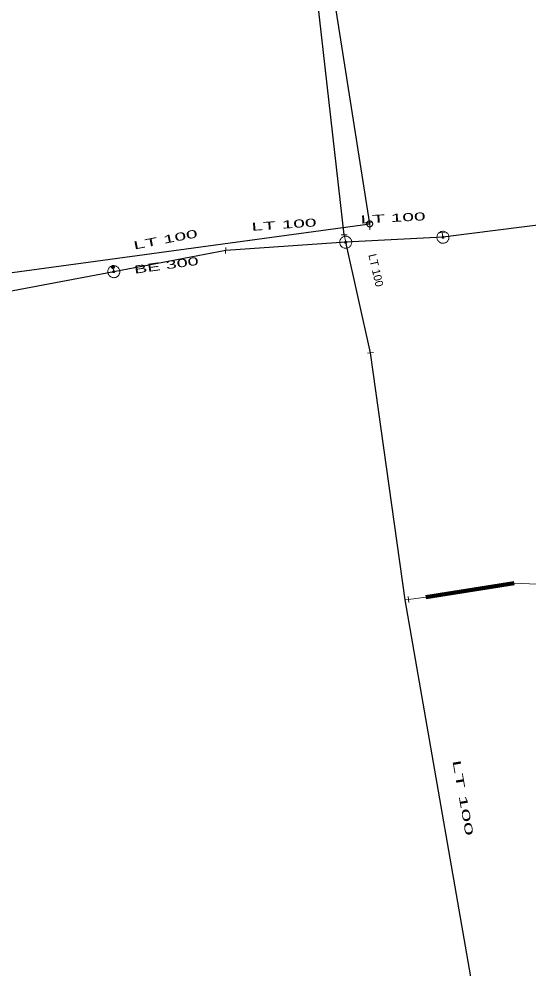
# Model space of a CAD drawing. Extents: x -687515 to -686506, y -974029 to -973461.
# Drawn here: x -687253.9 to -687211.4, y -973757.5 to -973678.4 of the extents above; entities that cross this region are included whole.
import ezdxf
from ezdxf.enums import TextEntityAlignment as Align

# ---------------------------------------------------------------- set-up
doc = ezdxf.new("R2010")
doc.units = 0
doc.header["$LTSCALE"] = 0.27
for name, color, linetype, lineweight in [('1', 7, 'Continuous', 13), ('13', 7, 'Continuous', 13), ('14', 7, 'Continuous', 25), ('17', 7, 'Continuous', 25), ('22', 7, 'Continuous', 13), ('3', 7, 'Continuous', 106), ('34', 7, 'Continuous', 13), ('47', 7, 'Continuous', 13), ('9', 7, 'Continuous', 13)]:
    doc.layers.add(name, color=color, linetype=linetype, lineweight=lineweight)

msp = doc.modelspace()

# ---------------------------------------------------------------- linework, layer by layer
at = {"layer": '13'}
msp.add_lwpolyline([(-687221.46, -973726.734), (-687220.01, -973726.539), (-687212.67, -973725.37), (-687210.76, -973725.46), (-687209.649, -973725.949), (-687209.469, -973727.689)], dxfattribs=at)
at = {"layer": '14'}
for p, q in [((-687224.684, -973695.454), (-687232.568, -973645.041)), ((-687258.796, -973700.107), (-687224.684, -973695.454))]:
    msp.add_line(p, q, dxfattribs=at)
at = {"layer": '14', "lineweight": 13}
for p, q in [((-687218.64, -973696.182), (-687218.589, -973696.579)), ((-687226.678, -973696.992), (-687226.809, -973696.379)), ((-687246.051, -973699.048), (-687245.977, -973699.441)), ((-687221.719, -973726.77), (-687221.46, -973726.734))]:
    msp.add_line(p, q, dxfattribs=at)
at = {"layer": '17'}
for p, q in [((-687152.206, -973687.982), (-687218.589, -973696.579)), ((-687226.678, -973696.992), (-687236.665, -973697.682)), ((-687218.589, -973696.579), (-687226.678, -973696.992)), ((-687224.609, -973706.199), (-687226.678, -973696.992)), ((-687236.665, -973697.682), (-687245.977, -973699.441))]:
    msp.add_line(p, q, dxfattribs=at)
for points in [[(-687226.809, -973696.379), (-687231.379, -973655.94), (-687231.546, -973653.623), (-687238.835, -973599.816), (-687148.873, -973581.4)], [(-687245.977, -973699.441), (-687281.864, -973706.221), (-687329.026, -973714.296), (-687356.324, -973710.759), (-687364.106, -973711.207)], [(-687215.094, -973764.848), (-687221.719, -973726.77), (-687224.609, -973706.199)]]:
    msp.add_lwpolyline(points, dxfattribs=at)
at = {"layer": '22'}
msp.add_line((-687224.683, -973695.202), (-687224.684, -973695.946), dxfattribs=at)
msp.add_lwpolyline([(-687224.432, -973695.454), (-687224.433, -973695.428), (-687224.437, -973695.402), (-687224.443, -973695.376), (-687224.453, -973695.352), (-687224.465, -973695.328), (-687224.479, -973695.306), (-687224.496, -973695.285), (-687224.514, -973695.267), (-687224.535, -973695.25), (-687224.557, -973695.236), (-687224.581, -973695.224), (-687224.605, -973695.214), (-687224.631, -973695.208), (-687224.657, -973695.204), (-687224.683, -973695.202), (-687224.709, -973695.203), (-687224.735, -973695.207), (-687224.761, -973695.213), (-687224.786, -973695.223), (-687224.809, -973695.235), (-687224.831, -973695.249), (-687224.852, -973695.266), (-687224.87, -973695.284), (-687224.887, -973695.305), (-687224.901, -973695.327), (-687224.913, -973695.351), (-687224.923, -973695.375), (-687224.93, -973695.401), (-687224.934, -973695.427), (-687224.936, -973695.453), (-687224.935, -973695.479), (-687224.931, -973695.505), (-687224.924, -973695.531), (-687224.914, -973695.556), (-687224.902, -973695.579), (-687224.888, -973695.601), (-687224.871, -973695.622), (-687224.853, -973695.64), (-687224.832, -973695.657), (-687224.81, -973695.671), (-687224.787, -973695.683), (-687224.762, -973695.693), (-687224.736, -973695.7), (-687224.71, -973695.704), (-687224.684, -973695.706), (-687224.658, -973695.705), (-687224.632, -973695.701), (-687224.606, -973695.694), (-687224.582, -973695.684), (-687224.558, -973695.672), (-687224.536, -973695.658), (-687224.515, -973695.641), (-687224.497, -973695.623), (-687224.48, -973695.602), (-687224.466, -973695.58), (-687224.454, -973695.557), (-687224.444, -973695.532), (-687224.438, -973695.506), (-687224.434, -973695.48)], close=True, dxfattribs=at)
at = {"layer": '3'}
msp.add_line((-687220.01, -973726.54), (-687212.67, -973725.37), dxfattribs=at)
at = {"layer": '3', "lineweight": 100}
msp.add_line((-687220.01, -973726.54), (-687212.67, -973725.37), dxfattribs=at)
at = {"layer": '34'}
for p, q in [((-687218.885, -973696.215), (-687218.394, -973696.148)), ((-687226.561, -973696.385), (-687227.056, -973696.372)), ((-687236.671, -973697.929), (-687236.658, -973697.434)), ((-687224.855, -973706.221), (-687224.362, -973706.176)), ((-687221.426, -973726.979), (-687221.493, -973726.488))]:
    msp.add_line(p, q, dxfattribs=at)
at = {"layer": '47'}
for points in [[(-687218.093, -973696.514), (-687218.102, -973696.463), (-687218.117, -973696.412), (-687218.137, -973696.365), (-687218.161, -973696.318), (-687218.191, -973696.275), (-687218.226, -973696.235), (-687218.264, -973696.199), (-687218.305, -973696.168), (-687218.349, -973696.14), (-687218.396, -973696.117), (-687218.446, -973696.099), (-687218.497, -973696.088), (-687218.548, -973696.08), (-687218.601, -973696.079), (-687218.653, -973696.083), (-687218.704, -973696.092), (-687218.755, -973696.107), (-687218.803, -973696.127), (-687218.849, -973696.151), (-687218.892, -973696.181), (-687218.932, -973696.216), (-687218.969, -973696.254), (-687219, -973696.295), (-687219.028, -973696.339), (-687219.05, -973696.386), (-687219.068, -973696.436), (-687219.08, -973696.487), (-687219.087, -973696.538), (-687219.088, -973696.591), (-687219.084, -973696.643), (-687219.075, -973696.694), (-687219.06, -973696.745), (-687219.041, -973696.794), (-687219.016, -973696.839), (-687218.986, -973696.882), (-687218.952, -973696.922), (-687218.914, -973696.959), (-687218.873, -973696.991), (-687218.828, -973697.018), (-687218.781, -973697.04), (-687218.731, -973697.058), (-687218.681, -973697.071), (-687218.629, -973697.077), (-687218.576, -973697.078), (-687218.524, -973697.074), (-687218.473, -973697.065), (-687218.422, -973697.05), (-687218.374, -973697.031), (-687218.328, -973697.006), (-687218.285, -973696.976), (-687218.245, -973696.942), (-687218.209, -973696.904), (-687218.177, -973696.863), (-687218.15, -973696.818), (-687218.127, -973696.771), (-687218.109, -973696.721), (-687218.097, -973696.671), (-687218.09, -973696.619), (-687218.089, -973696.566)], [(-687226.182, -973696.927), (-687226.191, -973696.876), (-687226.206, -973696.825), (-687226.226, -973696.778), (-687226.25, -973696.731), (-687226.28, -973696.688), (-687226.315, -973696.648), (-687226.353, -973696.612), (-687226.394, -973696.581), (-687226.438, -973696.553), (-687226.485, -973696.53), (-687226.535, -973696.512), (-687226.586, -973696.501), (-687226.637, -973696.493), (-687226.69, -973696.492), (-687226.742, -973696.496), (-687226.793, -973696.505), (-687226.844, -973696.52), (-687226.892, -973696.54), (-687226.938, -973696.564), (-687226.981, -973696.594), (-687227.021, -973696.629), (-687227.058, -973696.667), (-687227.089, -973696.708), (-687227.117, -973696.752), (-687227.139, -973696.799), (-687227.157, -973696.849), (-687227.169, -973696.9), (-687227.176, -973696.951), (-687227.177, -973697.004), (-687227.173, -973697.056), (-687227.164, -973697.107), (-687227.149, -973697.158), (-687227.13, -973697.207), (-687227.105, -973697.252), (-687227.075, -973697.295), (-687227.041, -973697.335), (-687227.003, -973697.372), (-687226.962, -973697.404), (-687226.917, -973697.431), (-687226.87, -973697.453), (-687226.82, -973697.471), (-687226.77, -973697.484), (-687226.718, -973697.49), (-687226.665, -973697.491), (-687226.613, -973697.487), (-687226.562, -973697.478), (-687226.511, -973697.463), (-687226.463, -973697.444), (-687226.417, -973697.419), (-687226.374, -973697.389), (-687226.334, -973697.355), (-687226.298, -973697.317), (-687226.266, -973697.276), (-687226.239, -973697.231), (-687226.216, -973697.184), (-687226.198, -973697.134), (-687226.186, -973697.084), (-687226.179, -973697.032), (-687226.178, -973696.979)], [(-687226.596, -973696.981), (-687226.597, -973696.972), (-687226.6, -973696.964), (-687226.603, -973696.957), (-687226.607, -973696.949), (-687226.612, -973696.942), (-687226.618, -973696.935), (-687226.624, -973696.929), (-687226.631, -973696.924), (-687226.638, -973696.92), (-687226.646, -973696.916), (-687226.654, -973696.913), (-687226.663, -973696.911), (-687226.671, -973696.91), (-687226.679, -973696.909), (-687226.688, -973696.91), (-687226.697, -973696.911), (-687226.705, -973696.914), (-687226.712, -973696.917), (-687226.72, -973696.921), (-687226.727, -973696.926), (-687226.734, -973696.932), (-687226.74, -973696.938), (-687226.745, -973696.945), (-687226.75, -973696.953), (-687226.753, -973696.96), (-687226.756, -973696.968), (-687226.758, -973696.977), (-687226.759, -973696.985), (-687226.76, -973696.993), (-687226.759, -973697.002), (-687226.758, -973697.011), (-687226.755, -973697.019), (-687226.752, -973697.026), (-687226.748, -973697.034), (-687226.743, -973697.041), (-687226.738, -973697.048), (-687226.731, -973697.054), (-687226.724, -973697.059), (-687226.716, -973697.064), (-687226.709, -973697.067), (-687226.701, -973697.07), (-687226.692, -973697.072), (-687226.684, -973697.073), (-687226.676, -973697.074), (-687226.667, -973697.073), (-687226.658, -973697.072), (-687226.65, -973697.069), (-687226.643, -973697.066), (-687226.635, -973697.062), (-687226.628, -973697.057), (-687226.621, -973697.052), (-687226.615, -973697.045), (-687226.61, -973697.038), (-687226.606, -973697.031), (-687226.602, -973697.023), (-687226.599, -973697.015), (-687226.597, -973697.006), (-687226.596, -973696.998), (-687226.595, -973696.99)], [(-687218.507, -973696.568), (-687218.508, -973696.559), (-687218.511, -973696.551), (-687218.514, -973696.544), (-687218.518, -973696.536), (-687218.523, -973696.529), (-687218.529, -973696.522), (-687218.535, -973696.516), (-687218.542, -973696.511), (-687218.549, -973696.507), (-687218.557, -973696.503), (-687218.565, -973696.5), (-687218.574, -973696.498), (-687218.582, -973696.497), (-687218.59, -973696.496), (-687218.599, -973696.497), (-687218.608, -973696.498), (-687218.616, -973696.501), (-687218.623, -973696.504), (-687218.631, -973696.508), (-687218.638, -973696.513), (-687218.645, -973696.519), (-687218.651, -973696.525), (-687218.656, -973696.532), (-687218.661, -973696.54), (-687218.664, -973696.547), (-687218.667, -973696.555), (-687218.669, -973696.564), (-687218.67, -973696.572), (-687218.671, -973696.58), (-687218.67, -973696.589), (-687218.669, -973696.598), (-687218.666, -973696.606), (-687218.663, -973696.613), (-687218.659, -973696.621), (-687218.654, -973696.628), (-687218.649, -973696.635), (-687218.642, -973696.641), (-687218.635, -973696.646), (-687218.627, -973696.651), (-687218.62, -973696.654), (-687218.612, -973696.657), (-687218.603, -973696.659), (-687218.595, -973696.66), (-687218.587, -973696.661), (-687218.578, -973696.66), (-687218.569, -973696.659), (-687218.561, -973696.656), (-687218.554, -973696.653), (-687218.546, -973696.649), (-687218.539, -973696.644), (-687218.532, -973696.639), (-687218.526, -973696.632), (-687218.521, -973696.625), (-687218.517, -973696.618), (-687218.513, -973696.61), (-687218.51, -973696.602), (-687218.508, -973696.593), (-687218.507, -973696.585), (-687218.506, -973696.577)], [(-687245.481, -973699.376), (-687245.49, -973699.325), (-687245.505, -973699.274), (-687245.525, -973699.227), (-687245.549, -973699.18), (-687245.579, -973699.137), (-687245.614, -973699.097), (-687245.652, -973699.061), (-687245.693, -973699.03), (-687245.737, -973699.002), (-687245.784, -973698.979), (-687245.834, -973698.961), (-687245.885, -973698.95), (-687245.936, -973698.942), (-687245.989, -973698.941), (-687246.041, -973698.945), (-687246.092, -973698.954), (-687246.143, -973698.969), (-687246.191, -973698.989), (-687246.237, -973699.013), (-687246.28, -973699.043), (-687246.32, -973699.078), (-687246.357, -973699.116), (-687246.388, -973699.157), (-687246.416, -973699.201), (-687246.438, -973699.248), (-687246.456, -973699.298), (-687246.468, -973699.349), (-687246.475, -973699.4), (-687246.476, -973699.453), (-687246.472, -973699.505), (-687246.463, -973699.556), (-687246.448, -973699.607), (-687246.429, -973699.656), (-687246.404, -973699.701), (-687246.374, -973699.744), (-687246.34, -973699.784), (-687246.302, -973699.821), (-687246.261, -973699.853), (-687246.216, -973699.88), (-687246.169, -973699.902), (-687246.119, -973699.92), (-687246.069, -973699.933), (-687246.017, -973699.939), (-687245.964, -973699.94), (-687245.912, -973699.936), (-687245.861, -973699.927), (-687245.81, -973699.912), (-687245.762, -973699.893), (-687245.716, -973699.868), (-687245.673, -973699.838), (-687245.633, -973699.804), (-687245.597, -973699.766), (-687245.565, -973699.725), (-687245.538, -973699.68), (-687245.515, -973699.633), (-687245.497, -973699.583), (-687245.485, -973699.533), (-687245.478, -973699.481), (-687245.477, -973699.428)], [(-687245.895, -973699.43), (-687245.896, -973699.421), (-687245.899, -973699.413), (-687245.902, -973699.406), (-687245.906, -973699.398), (-687245.911, -973699.391), (-687245.917, -973699.384), (-687245.923, -973699.378), (-687245.93, -973699.373), (-687245.937, -973699.369), (-687245.945, -973699.365), (-687245.953, -973699.362), (-687245.962, -973699.36), (-687245.97, -973699.359), (-687245.978, -973699.358), (-687245.987, -973699.359), (-687245.996, -973699.36), (-687246.004, -973699.363), (-687246.011, -973699.366), (-687246.019, -973699.37), (-687246.026, -973699.375), (-687246.033, -973699.381), (-687246.039, -973699.387), (-687246.044, -973699.394), (-687246.049, -973699.402), (-687246.052, -973699.409), (-687246.055, -973699.417), (-687246.057, -973699.426), (-687246.058, -973699.434), (-687246.059, -973699.442), (-687246.058, -973699.451), (-687246.057, -973699.46), (-687246.054, -973699.468), (-687246.051, -973699.475), (-687246.047, -973699.483), (-687246.042, -973699.49), (-687246.037, -973699.497), (-687246.03, -973699.503), (-687246.023, -973699.508), (-687246.015, -973699.513), (-687246.008, -973699.516), (-687246, -973699.519), (-687245.991, -973699.521), (-687245.983, -973699.522), (-687245.975, -973699.523), (-687245.966, -973699.522), (-687245.957, -973699.521), (-687245.949, -973699.518), (-687245.942, -973699.515), (-687245.934, -973699.511), (-687245.927, -973699.506), (-687245.92, -973699.501), (-687245.914, -973699.494), (-687245.909, -973699.487), (-687245.905, -973699.48), (-687245.901, -973699.472), (-687245.898, -973699.464), (-687245.896, -973699.455), (-687245.895, -973699.447), (-687245.894, -973699.439)]]:
    msp.add_lwpolyline(points, close=True, dxfattribs=at)
at = {"layer": '9'}
for points in [[(-687245.924, -973699.048), (-687245.926, -973699.034), (-687245.928, -973699.022), (-687245.931, -973699.009), (-687245.936, -973698.997), (-687245.941, -973698.985), (-687245.949, -973698.973), (-687245.956, -973698.963), (-687245.967, -973698.953), (-687245.977, -973698.946), (-687245.988, -973698.938), (-687246, -973698.933), (-687246.012, -973698.928), (-687246.025, -973698.924), (-687246.038, -973698.923), (-687246.051, -973698.921), (-687246.064, -973698.923), (-687246.076, -973698.924), (-687246.09, -973698.928), (-687246.102, -973698.933), (-687246.114, -973698.938), (-687246.125, -973698.946), (-687246.135, -973698.953), (-687246.145, -973698.963), (-687246.152, -973698.973), (-687246.16, -973698.985), (-687246.166, -973698.997), (-687246.171, -973699.009), (-687246.174, -973699.022), (-687246.176, -973699.034), (-687246.177, -973699.048), (-687246.176, -973699.061), (-687246.174, -973699.073), (-687246.171, -973699.087), (-687246.166, -973699.098), (-687246.16, -973699.11), (-687246.152, -973699.122), (-687246.145, -973699.132), (-687246.135, -973699.142), (-687246.125, -973699.149), (-687246.114, -973699.157), (-687246.102, -973699.163), (-687246.09, -973699.168), (-687246.076, -973699.171), (-687246.064, -973699.173), (-687246.051, -973699.174), (-687246.038, -973699.173), (-687246.025, -973699.171), (-687246.012, -973699.168), (-687246, -973699.163), (-687245.988, -973699.157), (-687245.977, -973699.149), (-687245.967, -973699.142), (-687245.956, -973699.132), (-687245.949, -973699.122), (-687245.941, -973699.11), (-687245.936, -973699.098), (-687245.931, -973699.087), (-687245.928, -973699.073), (-687245.926, -973699.061)], [(-687245.945, -973699.048), (-687245.945, -973699.036), (-687245.946, -973699.026), (-687245.95, -973699.014), (-687245.954, -973699.005), (-687245.959, -973698.995), (-687245.965, -973698.985), (-687245.972, -973698.977), (-687245.98, -973698.968), (-687245.989, -973698.962), (-687245.998, -973698.956), (-687246.008, -973698.951), (-687246.017, -973698.946), (-687246.029, -973698.943), (-687246.039, -973698.941), (-687246.051, -973698.941), (-687246.062, -973698.941), (-687246.073, -973698.943), (-687246.084, -973698.946), (-687246.093, -973698.951), (-687246.103, -973698.956), (-687246.113, -973698.962), (-687246.122, -973698.968), (-687246.13, -973698.977), (-687246.137, -973698.985), (-687246.142, -973698.995), (-687246.147, -973699.005), (-687246.152, -973699.014), (-687246.155, -973699.026), (-687246.157, -973699.036), (-687246.157, -973699.048), (-687246.157, -973699.059), (-687246.155, -973699.07), (-687246.152, -973699.081), (-687246.147, -973699.09), (-687246.142, -973699.1), (-687246.137, -973699.11), (-687246.13, -973699.119), (-687246.122, -973699.127), (-687246.113, -973699.134), (-687246.103, -973699.139), (-687246.093, -973699.144), (-687246.084, -973699.149), (-687246.073, -973699.152), (-687246.062, -973699.154), (-687246.051, -973699.154), (-687246.039, -973699.154), (-687246.029, -973699.152), (-687246.017, -973699.149), (-687246.008, -973699.144), (-687245.998, -973699.139), (-687245.989, -973699.134), (-687245.98, -973699.127), (-687245.972, -973699.119), (-687245.965, -973699.11), (-687245.959, -973699.1), (-687245.954, -973699.09), (-687245.95, -973699.081), (-687245.946, -973699.07), (-687245.945, -973699.059)], [(-687245.963, -973699.048), (-687245.965, -973699.039), (-687245.966, -973699.029), (-687245.968, -973699.021), (-687245.972, -973699.012), (-687245.976, -973699.005), (-687245.981, -973698.997), (-687245.987, -973698.99), (-687245.993, -973698.983), (-687246, -973698.978), (-687246.008, -973698.973), (-687246.016, -973698.968), (-687246.024, -973698.965), (-687246.032, -973698.963), (-687246.042, -973698.962), (-687246.051, -973698.96), (-687246.059, -973698.962), (-687246.069, -973698.963), (-687246.078, -973698.965), (-687246.086, -973698.968), (-687246.093, -973698.973), (-687246.102, -973698.978), (-687246.108, -973698.983), (-687246.115, -973698.99), (-687246.12, -973698.997), (-687246.125, -973699.005), (-687246.13, -973699.012), (-687246.133, -973699.021), (-687246.136, -973699.029), (-687246.137, -973699.039), (-687246.138, -973699.048), (-687246.137, -973699.056), (-687246.136, -973699.066), (-687246.133, -973699.075), (-687246.13, -973699.083), (-687246.125, -973699.09), (-687246.12, -973699.098), (-687246.115, -973699.105), (-687246.108, -973699.112), (-687246.102, -973699.117), (-687246.093, -973699.122), (-687246.086, -973699.127), (-687246.078, -973699.13), (-687246.069, -973699.132), (-687246.059, -973699.134), (-687246.051, -973699.135), (-687246.042, -973699.134), (-687246.032, -973699.132), (-687246.024, -973699.13), (-687246.016, -973699.127), (-687246.008, -973699.122), (-687246, -973699.117), (-687245.993, -973699.112), (-687245.987, -973699.105), (-687245.981, -973699.098), (-687245.976, -973699.09), (-687245.972, -973699.083), (-687245.968, -973699.075), (-687245.966, -973699.066), (-687245.965, -973699.056)], [(-687245.983, -973699.048), (-687245.983, -973699.041), (-687245.986, -973699.034), (-687245.987, -973699.027), (-687245.99, -973699.021), (-687245.993, -973699.014), (-687245.997, -973699.009), (-687246, -973699.002), (-687246.005, -973698.997), (-687246.012, -973698.994), (-687246.017, -973698.99), (-687246.024, -973698.987), (-687246.03, -973698.983), (-687246.037, -973698.983), (-687246.044, -973698.98), (-687246.051, -973698.98), (-687246.058, -973698.98), (-687246.065, -973698.983), (-687246.071, -973698.983), (-687246.078, -973698.987), (-687246.085, -973698.99), (-687246.09, -973698.994), (-687246.096, -973698.997), (-687246.101, -973699.002), (-687246.105, -973699.009), (-687246.108, -973699.014), (-687246.112, -973699.021), (-687246.115, -973699.027), (-687246.117, -973699.034), (-687246.118, -973699.041), (-687246.118, -973699.048), (-687246.118, -973699.054), (-687246.117, -973699.061), (-687246.115, -973699.068), (-687246.112, -973699.075), (-687246.108, -973699.081), (-687246.105, -973699.087), (-687246.101, -973699.093), (-687246.096, -973699.098), (-687246.09, -973699.102), (-687246.085, -973699.105), (-687246.078, -973699.108), (-687246.071, -973699.112), (-687246.065, -973699.114), (-687246.058, -973699.115), (-687246.051, -973699.115), (-687246.044, -973699.115), (-687246.037, -973699.114), (-687246.03, -973699.112), (-687246.024, -973699.108), (-687246.017, -973699.105), (-687246.012, -973699.102), (-687246.005, -973699.098), (-687246, -973699.093), (-687245.997, -973699.087), (-687245.993, -973699.081), (-687245.99, -973699.075), (-687245.987, -973699.068), (-687245.986, -973699.061), (-687245.983, -973699.054)], [(-687246.004, -973699.048), (-687246.004, -973699.043), (-687246.005, -973699.038), (-687246.005, -973699.032), (-687246.008, -973699.029), (-687246.01, -973699.024), (-687246.013, -973699.019), (-687246.016, -973699.017), (-687246.02, -973699.012), (-687246.022, -973699.01), (-687246.027, -973699.007), (-687246.032, -973699.005), (-687246.036, -973699.002), (-687246.041, -973699.002), (-687246.046, -973699), (-687246.051, -973699), (-687246.056, -973699), (-687246.061, -973699.002), (-687246.066, -973699.002), (-687246.07, -973699.005), (-687246.075, -973699.007), (-687246.079, -973699.01), (-687246.083, -973699.012), (-687246.086, -973699.017), (-687246.088, -973699.019), (-687246.092, -973699.024), (-687246.093, -973699.029), (-687246.096, -973699.032), (-687246.097, -973699.038), (-687246.098, -973699.043), (-687246.098, -973699.048), (-687246.098, -973699.053), (-687246.097, -973699.058), (-687246.096, -973699.063), (-687246.093, -973699.066), (-687246.092, -973699.071), (-687246.088, -973699.076), (-687246.086, -973699.08), (-687246.083, -973699.083), (-687246.079, -973699.085), (-687246.075, -973699.088), (-687246.07, -973699.09), (-687246.066, -973699.093), (-687246.061, -973699.093), (-687246.056, -973699.095), (-687246.051, -973699.095), (-687246.046, -973699.095), (-687246.041, -973699.093), (-687246.036, -973699.093), (-687246.032, -973699.09), (-687246.027, -973699.088), (-687246.022, -973699.085), (-687246.02, -973699.083), (-687246.016, -973699.08), (-687246.013, -973699.076), (-687246.01, -973699.071), (-687246.008, -973699.066), (-687246.005, -973699.063), (-687246.005, -973699.058), (-687246.004, -973699.053)], [(-687246.024, -973699.048), (-687246.024, -973699.044), (-687246.024, -973699.041), (-687246.025, -973699.039), (-687246.026, -973699.036), (-687246.027, -973699.034), (-687246.029, -973699.032), (-687246.031, -973699.029), (-687246.032, -973699.027), (-687246.035, -973699.026), (-687246.037, -973699.024), (-687246.039, -973699.022), (-687246.043, -973699.022), (-687246.044, -973699.021), (-687246.048, -973699.021), (-687246.051, -973699.021), (-687246.054, -973699.021), (-687246.057, -973699.021), (-687246.059, -973699.022), (-687246.062, -973699.022), (-687246.065, -973699.024), (-687246.066, -973699.026), (-687246.07, -973699.027), (-687246.071, -973699.029), (-687246.073, -973699.032), (-687246.075, -973699.034), (-687246.076, -973699.036), (-687246.076, -973699.039), (-687246.078, -973699.041), (-687246.078, -973699.044), (-687246.079, -973699.048), (-687246.078, -973699.051), (-687246.078, -973699.054), (-687246.076, -973699.056), (-687246.076, -973699.059), (-687246.075, -973699.061), (-687246.073, -973699.063), (-687246.071, -973699.066), (-687246.07, -973699.068), (-687246.066, -973699.07), (-687246.065, -973699.071), (-687246.062, -973699.073), (-687246.059, -973699.073), (-687246.057, -973699.075), (-687246.054, -973699.075), (-687246.051, -973699.076), (-687246.048, -973699.075), (-687246.044, -973699.075), (-687246.043, -973699.073), (-687246.039, -973699.073), (-687246.037, -973699.071), (-687246.035, -973699.07), (-687246.032, -973699.068), (-687246.031, -973699.066), (-687246.029, -973699.063), (-687246.027, -973699.061), (-687246.026, -973699.059), (-687246.025, -973699.056), (-687246.024, -973699.054), (-687246.024, -973699.051)], [(-687246.043, -973699.048), (-687246.043, -973699.046), (-687246.043, -973699.046), (-687246.044, -973699.046), (-687246.044, -973699.044), (-687246.044, -973699.044), (-687246.044, -973699.043), (-687246.044, -973699.043), (-687246.046, -973699.041), (-687246.046, -973699.041), (-687246.047, -973699.041), (-687246.048, -973699.041), (-687246.049, -973699.041), (-687246.049, -973699.039), (-687246.049, -973699.039), (-687246.051, -973699.039), (-687246.052, -973699.039), (-687246.053, -973699.039), (-687246.053, -973699.041), (-687246.054, -973699.041), (-687246.054, -973699.041), (-687246.056, -973699.041), (-687246.056, -973699.041), (-687246.057, -973699.043), (-687246.057, -973699.043), (-687246.058, -973699.044), (-687246.058, -973699.044), (-687246.059, -973699.046), (-687246.059, -973699.046), (-687246.059, -973699.046), (-687246.059, -973699.048), (-687246.059, -973699.049), (-687246.059, -973699.049), (-687246.059, -973699.049), (-687246.058, -973699.051), (-687246.058, -973699.051), (-687246.057, -973699.053), (-687246.057, -973699.053), (-687246.056, -973699.054), (-687246.056, -973699.054), (-687246.054, -973699.054), (-687246.054, -973699.054), (-687246.053, -973699.056), (-687246.053, -973699.056), (-687246.052, -973699.056), (-687246.051, -973699.056), (-687246.049, -973699.056), (-687246.049, -973699.056), (-687246.049, -973699.056), (-687246.048, -973699.054), (-687246.047, -973699.054), (-687246.046, -973699.054), (-687246.046, -973699.054), (-687246.044, -973699.053), (-687246.044, -973699.053), (-687246.044, -973699.051), (-687246.044, -973699.051), (-687246.044, -973699.049), (-687246.043, -973699.049), (-687246.043, -973699.049)]]:
    msp.add_lwpolyline(points, close=True, dxfattribs=at)

# ---------------------------------------------------------------- texts
at = {"layer": '1'}
for s, rotation, width, p in [('LT 100', 3, 1.95, (-687222.722, -973695.297)), ('LT 100', 4, 1.95, (-687231.79, -973695.852)), ('LT 100', 11, 1.95, (-687241.613, -973697.083)), ('BE 300', 8, 1.85, (-687241.559, -973699.238)), ('LT 100', 280, 2.3, (-687217.247, -973743.312))]:
    msp.add_text(s, height=0.6667, rotation=rotation, dxfattribs=dict(at, width=width)).set_placement(p, align=Align.CENTER)
msp.add_text('LT 100', height=0.6667, rotation=283, dxfattribs=at).set_placement((-687224.483, -973699.399), align=Align.CENTER)

doc.saveas('drawing.dxf')
